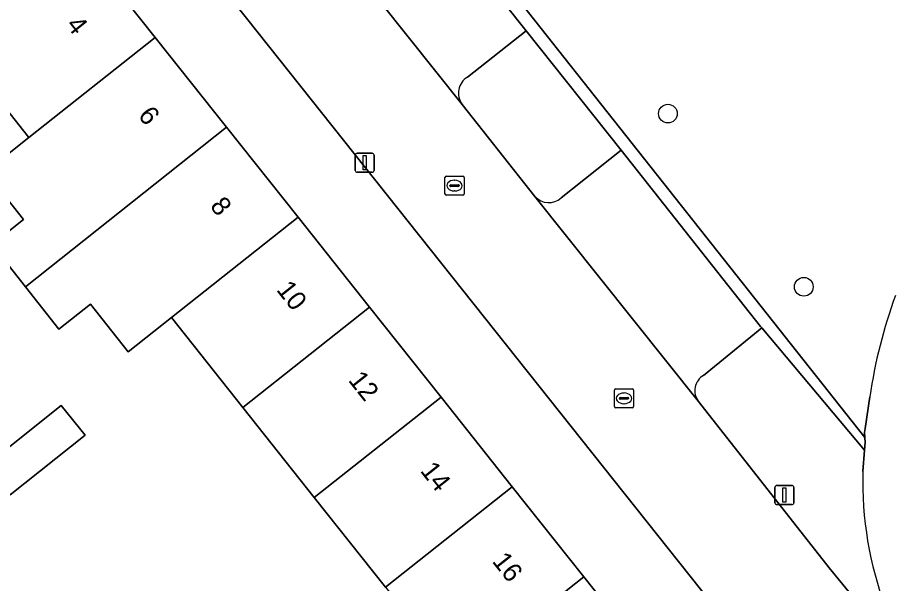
# Model space of a CAD drawing. Extents: x 157320 to 158835, y 386650 to 388491.
# Drawn here: x 157790.58 to 157836.19, y 387525.96 to 387555.56 of the extents above; entities that cross this region are included whole.
import ezdxf

# ---------------------------------------------------------------- set-up
doc = ezdxf.new("R2010")
doc.units = 0
for name, color, linetype in [('IMGEO_Boom', 7, 'Continuous'), ('IMGEO_Erf', 7, 'Continuous'), ('IMGEO_Groenvoorziening', 7, 'Continuous'), ('IMGEO_Haag', 7, 'Continuous'), ('IMGEO_Kolk', 7, 'Continuous'), ('IMGEO_Lichtmast', 7, 'Continuous'), ('IMGEO_Pand', 7, 'Continuous'), ('IMGEO_Pand_nummerreeks', 7, 'Continuous'), ('IMGEO_Parkeervlak_open', 7, 'Continuous'), ('IMGEO_Rijbaan_lokaal_open', 7, 'Continuous'), ('IMGEO_Voetpad_open', 7, 'Continuous')]:
    doc.layers.add(name, color=color, linetype=linetype)

msp = doc.modelspace()

# ---------------------------------------------------------------- linework, layer by layer
at = {"layer": 'IMGEO_Boom'}
for centre in [(157824.561, 387550.534), (157831.659, 387541.478)]:
    msp.add_circle(centre, 0.489, dxfattribs=at)
at = {"layer": 'IMGEO_Erf'}
for points in [[(157819.244, 387513.872), (157824.278, 387517.873), (157829.287, 387521.854), (157827.412, 387524.212), (157792.348, 387568.39), (157742.039, 387528.565), (157744.071, 387526.007), (157755.546, 387511.564), (157757.331, 387512.983), (157759.693, 387514.861), (157761.245, 387516.095), (157763.827, 387518.148), (157766.927, 387514.234), (157764.333, 387512.18), (157762.786, 387510.955), (157760.42, 387509.082), (157758.638, 387507.671), (157762.365, 387502.98), (157760.625, 387501.492), (157769.911, 387489.771), (157777.254, 387480.504), (157788.46, 387489.409), (157801.788, 387500), (157809.599, 387506.206)], [(157790.198, 387530.591), (157788.95, 387532.154), (157792.866, 387535.279), (157794.114, 387533.715)]]:
    msp.add_lwpolyline(points, close=True, dxfattribs=at)
for points in [[(157790.193, 387564.082), (157794.04, 387559.231), (157797.776, 387554.523), (157801.506, 387549.824), (157805.243, 387545.115), (157808.973, 387540.415), (157812.709, 387535.708), (157816.434, 387531.015), (157820.17, 387526.308), (157824.005, 387521.476)], [(157809.816, 387525.766), (157806.09, 387530.468), (157802.364, 387535.17), (157798.632, 387539.879), (157796.373, 387538.077), (157794.397, 387540.57), (157792.753, 387539.263), (157791.002, 387541.473), (157789.25, 387543.684), (157790.894, 387544.991), (157788.916, 387547.487), (157791.179, 387549.284), (157787.453, 387553.986)]]:
    msp.add_lwpolyline(points, dxfattribs=at)
at = {"layer": 'IMGEO_Groenvoorziening'}
for points in [[(157803.282, 387575.231), (157803.21, 387574.813), (157803.815, 387573.954), (157804.139, 387572.463), (157834.85, 387533.597), (157834.837, 387533.856), (157834.867, 387534.06), (157835.108, 387535.724)], [(157802.873, 387572.88), (157805.996, 387568.908), (157809.751, 387564.168), (157817.15, 387554.871), (157822.119, 387548.629), (157829.406, 387539.401), (157829.466, 387539.329), (157834.833, 387532.936), (157834.863, 387533.34), (157834.85, 387533.597), (157804.139, 387572.463)], [(157817.15, 387554.871), (157814.089, 387552.441)], [(157818.99, 387546.125), (157822.119, 387548.629), (157817.15, 387554.871)], [(157813.81, 387551.018), (157817.616, 387546.205)], [(157829.466, 387539.329), (157826.425, 387536.842)], [(157834.751, 387531.811), (157834.833, 387532.936), (157829.466, 387539.329)], [(157826.156, 387535.484), (157832.986, 387526.787), (157835.189, 387524.078), (157835.938, 387524.682)]]:
    msp.add_lwpolyline(points, dxfattribs=at)
for centre, radius, start, end in [((157814.6, 387551.602), 0.982, 121.3478, 216.4662), ((157818.343, 387546.857), 0.977, 221.8946, 311.4409), ((157862.045, 387531.762), 27.227, 160.1061, 171.6333), ((157826.878, 387536.047), 0.915, 119.6607, 217.9305), ((157853.395, 387531.252), 18.653, 178.2827, 200.6237)]:
    msp.add_arc(centre, radius, start, end, dxfattribs=at)
at = {"layer": 'IMGEO_Haag'}
msp.add_lwpolyline([(157802.873, 387572.88), (157805.996, 387568.908), (157809.751, 387564.168), (157817.15, 387554.871), (157822.119, 387548.629), (157829.406, 387539.401), (157829.466, 387539.329), (157834.833, 387532.936), (157834.863, 387533.34), (157834.85, 387533.597), (157804.139, 387572.463)], dxfattribs=at)
at = {"layer": 'IMGEO_Kolk'}
for p, q in [((157812.915, 387546.342), (157812.915, 387547.194)), ((157812.99, 387547.268), (157813.842, 387547.268)), ((157813.403, 387547.048), (157813.428, 387547.048)), ((157813.916, 387547.194), (157813.916, 387546.342)), ((157813.174, 387546.762), (157813.174, 387546.774)), ((157813.612, 387546.725), (157813.214, 387546.725)), ((157813.217, 387546.811), (157813.615, 387546.811)), ((157813.426, 387546.488), (157813.401, 387546.488)), ((157813.658, 387546.774), (157813.658, 387546.762)), ((157813.842, 387546.268), (157812.99, 387546.268)), ((157821.767, 387535.219), (157821.767, 387536.071)), ((157821.842, 387536.145), (157822.694, 387536.145)), ((157822.255, 387535.925), (157822.28, 387535.925)), ((157822.768, 387536.071), (157822.768, 387535.219)), ((157822.026, 387535.639), (157822.026, 387535.651)), ((157822.464, 387535.602), (157822.066, 387535.602)), ((157822.069, 387535.688), (157822.467, 387535.688)), ((157822.51, 387535.651), (157822.51, 387535.639)), ((157822.694, 387535.145), (157821.842, 387535.145)), ((157822.278, 387535.365), (157822.253, 387535.365))]:
    msp.add_line(p, q, dxfattribs=at)
for points in [[(157812.915, 387546.342), (157812.915, 387547.194)], [(157812.99, 387547.268), (157813.842, 387547.268)], [(157813.916, 387547.194), (157813.916, 387546.342)], [(157813.842, 387546.268), (157812.99, 387546.268)], [(157821.767, 387535.219), (157821.767, 387536.071)], [(157821.842, 387536.145), (157822.694, 387536.145)], [(157822.768, 387536.071), (157822.768, 387535.219)], [(157822.694, 387535.145), (157821.842, 387535.145)]]:
    msp.add_lwpolyline(points, dxfattribs=at)
for centre, radius, start, end in [((157812.992, 387547.192), 0.0765, 91.552, 178.448), ((157812.992, 387547.192), 0.0765, 91.552, 178.448), ((157813.84, 387547.192), 0.0765, 1.552, 88.448), ((157813.84, 387547.192), 0.0765, 1.552, 88.448), ((157813.214, 387546.771), 0.0403, 85.8775, 175.7526), ((157813.211, 387546.761), 0.0366, 178.938, 274.7102), ((157813.615, 387546.768), 0.043, 264.8664, 352.4533), ((157813.619, 387546.773), 0.0386, 1.7309, 96.639), ((157812.992, 387546.344), 0.0765, 181.552, 268.448), ((157812.992, 387546.344), 0.0765, 181.552, 268.448), ((157813.84, 387546.344), 0.0765, 271.552, 358.448), ((157813.84, 387546.344), 0.0765, 271.552, 358.448), ((157821.844, 387536.069), 0.0765, 91.552, 178.448), ((157821.844, 387536.069), 0.0765, 91.552, 178.448), ((157822.692, 387536.069), 0.0765, 1.552, 88.448), ((157822.692, 387536.069), 0.0765, 1.552, 88.448), ((157822.066, 387535.648), 0.0403, 85.8775, 175.7526), ((157822.063, 387535.638), 0.0366, 178.938, 274.7102), ((157822.467, 387535.645), 0.043, 264.8664, 352.4533), ((157822.471, 387535.65), 0.0386, 1.7309, 96.639), ((157821.844, 387535.221), 0.0765, 181.552, 268.448), ((157821.844, 387535.221), 0.0765, 181.552, 268.448), ((157822.692, 387535.221), 0.0765, 271.552, 358.448), ((157822.692, 387535.221), 0.0765, 271.552, 358.448)]:
    msp.add_arc(centre, radius, start, end, dxfattribs=at)
for centre, major_axis, ratio, start_param, end_param in [((157813.402, 387546.768), (-0.387, 0.002), 0.722429, 4.712389, 7.853982), ((157813.427, 387546.768), (-0.39, 0.002), 0.717154, 1.570796, 4.712389), ((157822.254, 387535.645), (-0.387, 0.002), 0.722429, 4.712389, 7.853982), ((157822.279, 387535.645), (-0.39, 0.002), 0.717154, 1.570796, 4.712389)]:
    msp.add_ellipse(centre, major_axis=major_axis, ratio=ratio, start_param=start_param, end_param=end_param, dxfattribs=at)
at = {"layer": 'IMGEO_Lichtmast'}
for p, q in [((157808.226, 387547.564), (157808.226, 387548.364)), ((157808.226, 387548.364), (157808.226, 387547.564)), ((157808.326, 387548.464), (157809.116, 387548.464)), ((157809.116, 387548.464), (157808.326, 387548.464)), ((157809.216, 387548.364), (157809.216, 387547.564)), ((157809.216, 387547.564), (157809.216, 387548.364)), ((157809.116, 387547.464), (157808.326, 387547.464)), ((157808.326, 387547.464), (157809.116, 387547.464)), ((157830.149, 387530.189), (157830.149, 387530.989)), ((157830.149, 387530.989), (157830.149, 387530.189)), ((157830.249, 387531.089), (157831.039, 387531.089)), ((157831.039, 387531.089), (157830.249, 387531.089)), ((157831.139, 387530.989), (157831.139, 387530.189)), ((157831.139, 387530.189), (157831.139, 387530.989)), ((157831.039, 387530.089), (157830.249, 387530.089)), ((157830.249, 387530.089), (157831.039, 387530.089))]:
    msp.add_line(p, q, dxfattribs=at)
for points in [[(157808.646, 387548.339), (157808.796, 387548.339), (157808.796, 387547.589), (157808.646, 387547.589), (157808.646, 387548.339)], [(157830.569, 387530.964), (157830.719, 387530.964), (157830.719, 387530.214), (157830.569, 387530.214), (157830.569, 387530.964)]]:
    msp.add_lwpolyline(points, dxfattribs=at)
for centre, start, end in [((157808.326, 387548.364), 90, 180), ((157808.326, 387548.364), 90, 180), ((157809.116, 387548.364), 0, 90), ((157809.116, 387548.364), 360, 90), ((157808.326, 387547.564), 180, 270), ((157808.326, 387547.564), 180, 270), ((157809.116, 387547.564), 270, 0), ((157809.116, 387547.564), 270, 0), ((157830.249, 387530.989), 90, 180), ((157830.249, 387530.989), 90, 180), ((157831.039, 387530.989), 0, 90), ((157831.039, 387530.989), 360, 90), ((157830.249, 387530.189), 180, 270), ((157830.249, 387530.189), 180, 270), ((157831.039, 387530.189), 270, 0), ((157831.039, 387530.189), 270, 0)]:
    msp.add_arc(centre, 0.1, start, end, dxfattribs=at)
at = {"layer": 'IMGEO_Pand'}
for points in [[(157791.179, 387549.284), (157797.776, 387554.523), (157794.04, 387559.231), (157787.453, 387553.986)], [(157801.506, 387549.824), (157797.776, 387554.523), (157791.179, 387549.284), (157788.916, 387547.487), (157790.894, 387544.991), (157789.25, 387543.684), (157791.002, 387541.473)], [(157805.243, 387545.115), (157801.506, 387549.824), (157791.002, 387541.473), (157792.753, 387539.263), (157794.397, 387540.57), (157796.373, 387538.077), (157798.632, 387539.879)], [(157805.243, 387545.115), (157798.632, 387539.879), (157802.364, 387535.17), (157808.973, 387540.415)], [(157806.09, 387530.468), (157812.709, 387535.708), (157808.973, 387540.415), (157802.364, 387535.17)], [(157809.816, 387525.766), (157816.434, 387531.015), (157812.709, 387535.708), (157806.09, 387530.468)], [(157790.198, 387530.591), (157794.114, 387533.715), (157792.866, 387535.279), (157788.95, 387532.154)], [(157809.816, 387525.766), (157813.549, 387521.057), (157820.17, 387526.308), (157816.434, 387531.015)], [(157820.17, 387526.308), (157813.549, 387521.057), (157817.387, 387516.213), (157818.667, 387517.228), (157822.421, 387520.215), (157824.005, 387521.476)]]:
    msp.add_lwpolyline(points, close=True, dxfattribs=at)
at = {"layer": 'IMGEO_Parkeervlak_open'}
for points in [[(157814.089, 387552.441), (157817.15, 387554.871), (157809.751, 387564.168), (157806.713, 387561.742)], [(157805.217, 387561.81), (157813.81, 387551.018)], [(157822.119, 387548.629), (157818.99, 387546.125)], [(157826.425, 387536.842), (157829.466, 387539.329), (157829.406, 387539.401), (157822.119, 387548.629)], [(157817.616, 387546.205), (157826.156, 387535.484)]]:
    msp.add_lwpolyline(points, dxfattribs=at)
for centre, radius, start, end in [((157814.6, 387551.602), 0.982, 121.3478, 216.4662), ((157818.343, 387546.857), 0.977, 221.8946, 311.4409), ((157826.878, 387536.047), 0.915, 119.6607, 217.9305)]:
    msp.add_arc(centre, radius, start, end, dxfattribs=at)
at = {"layer": 'IMGEO_Rijbaan_lokaal_open'}
msp.add_lwpolyline([(157802.855, 387573.642), (157803.031, 387574.082), (157803.067, 387574.191), (157800.167, 387574.541), (157792.348, 387568.39), (157827.412, 387524.212), (157829.287, 387521.854), (157830.517, 387520.307), (157835.189, 387524.078), (157832.986, 387526.787), (157826.156, 387535.484), (157817.616, 387546.205), (157813.81, 387551.018), (157805.217, 387561.81)], dxfattribs=at)
at = {"layer": 'IMGEO_Voetpad_open'}
msp.add_lwpolyline([(157835.108, 387535.724), (157834.867, 387534.06), (157834.837, 387533.856), (157834.85, 387533.597), (157834.863, 387533.34), (157834.833, 387532.936), (157834.751, 387531.811)], dxfattribs=at)
for centre, radius, start, end in [((157862.045, 387531.762), 27.227, 160.1061, 171.6333), ((157853.395, 387531.252), 18.653, 178.2827, 200.6237)]:
    msp.add_arc(centre, radius, start, end, dxfattribs=at)

# ---------------------------------------------------------------- texts
at = {"layer": 'IMGEO_Pand_nummerreeks'}
for s, rotation, p in [('4', 308.438, (157793.088, 387555.155)), ('6', 308.4395, (157796.845, 387550.421)), ('8', 308.4395, (157800.605, 387545.684)), ('10', 308.438, (157804.074, 387541.312)), ('12', 308.438, (157807.827, 387536.583)), ('14', 308.438, (157811.586, 387531.847)), ('16', 308.438, (157815.343, 387527.113))]:
    msp.add_text(s, height=1, rotation=rotation, dxfattribs=at).set_placement(p)

doc.saveas('drawing.dxf')
